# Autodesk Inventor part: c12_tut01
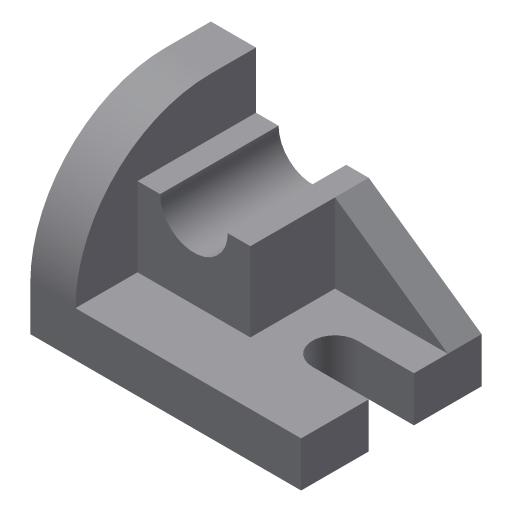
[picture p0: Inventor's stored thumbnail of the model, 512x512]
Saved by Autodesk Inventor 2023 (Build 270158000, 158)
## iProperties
Shininess: 77.0
Length Units: 11269
Angle Units: 11279
Time Units: 11290
Mass Units: 11283
Length Display Precision: 3
Angle Display Precision: 2
Created: 2001-11
Part Number: c12_tut01
Document SubType Name: Modeling
Designer: Renu Muthoo
Density: 1 g/cm^3
Material: Generic
Appearance: Default
Density: 0.0
Volumn: 0.0
Area: 0.0
PropertySet Name: Model Information
Control State: 0
Master: False
Checked Out: False
Author: Renu Muthoo
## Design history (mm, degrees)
sketch "Sketch1"
  geometry: L1 (-48, 36)-(48, 36); L2 (48, -28)-(-48, -28); L3 (-48, -28)-(-48, 36); L4 (48, 12)-(28, 12); L5 (28, -4)-(48, -4); L6 (48, 36)-(48, 12); L7 (48, -4)-(48, -28); A1 r 8 centre (28, 4) between (28, 12) and (28, -4)
  constraints: 14 end point, 4 parallel, 3 perpendicular, 2 point on circle, 2 tangent, 1 centre point, 1 collinear, 1 horizontal
  dimensions: "d0" = 96 distance of L2.start L2.end; "d1" = 64 distance of L2.end L1.start; "d2" = 20 distance of L4.start L4.end; "d3" = 24 distance between parallel lines of L2 L5; "d4" = 16 distance between parallel lines of L4 L5
extrude "Extrusion1" new body sketch "Sketch1" distance "d5" = 16; taper "d6" = 0 deg
sketch "Sketch2"
  geometry: L1 (16, 64)-(64, 64); L2 (64, 64)-(64, 48); L3 (16, 0)-(16, 0); L4 (16, 0)-(16, 64); L5 (0, 64)-(16, 64) reference; L6 (16, 0)-(16, 64) reference; L7 (0, 0)-(16, 0) reference; L8 (0, 0)-(0, 64) reference; A1 r 48 centre (16, 48) between (16, 0) and (64, 48)
  constraints: 8 end point, 3 collinear, 3 perpendicular, 2 point on circle, 2 tangent, 1 centre point, 1 horizontal
  dimensions: "d7" = 64 distance between parallel lines of L2 L8; "d8" = 48 radius of A1
extrude "Extrusion2" join sketch "Sketch2" distance "d9" = 16; taper "d10" = 0 deg
sketch "Sketch3"
  geometry: L1 (16, -44)-(16, -16); L2 (16, -16)-(56, -16); L3 (56, -16)-(56, -44); L4 (56, -44)-(48, -44); L5 (24, -44)-(16, -44); L6 (16, -64)-(16, -16) reference; L7 (16, -16)-(96, -16) reference; A1 r 12 centre (36, -44) between (48, -44) and (24, -44)
  constraints: 10 end point, 3 collinear, 3 parallel, 2 equal length, 2 point on circle, 1 centre point, 1 perpendicular, 1 point on line, 1 vertical
  dimensions: "d11" = 28 distance of L2.end L3.end; "d12" = 8 distance of L3.end L4.end; "d13" = 24 distance of L5.start L4.end
extrude "Extrusion3" join sketch "Sketch3" distance "d14" = 42; taper "d15" = 0 deg
sketch "Sketch4"
  geometry: L1 (56, -16)-(96, -16) reference; L2 (56, -16)-(56, -44) reference; L3 (96, -16)-(56, -44)
  constraints: 2 end point
extrude "Extrusion4" join sketch "Sketch4" distance "d16" = 12; taper "d17" = 0 deg
body "Solid1"
